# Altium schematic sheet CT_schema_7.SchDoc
size 278 x 170 mm
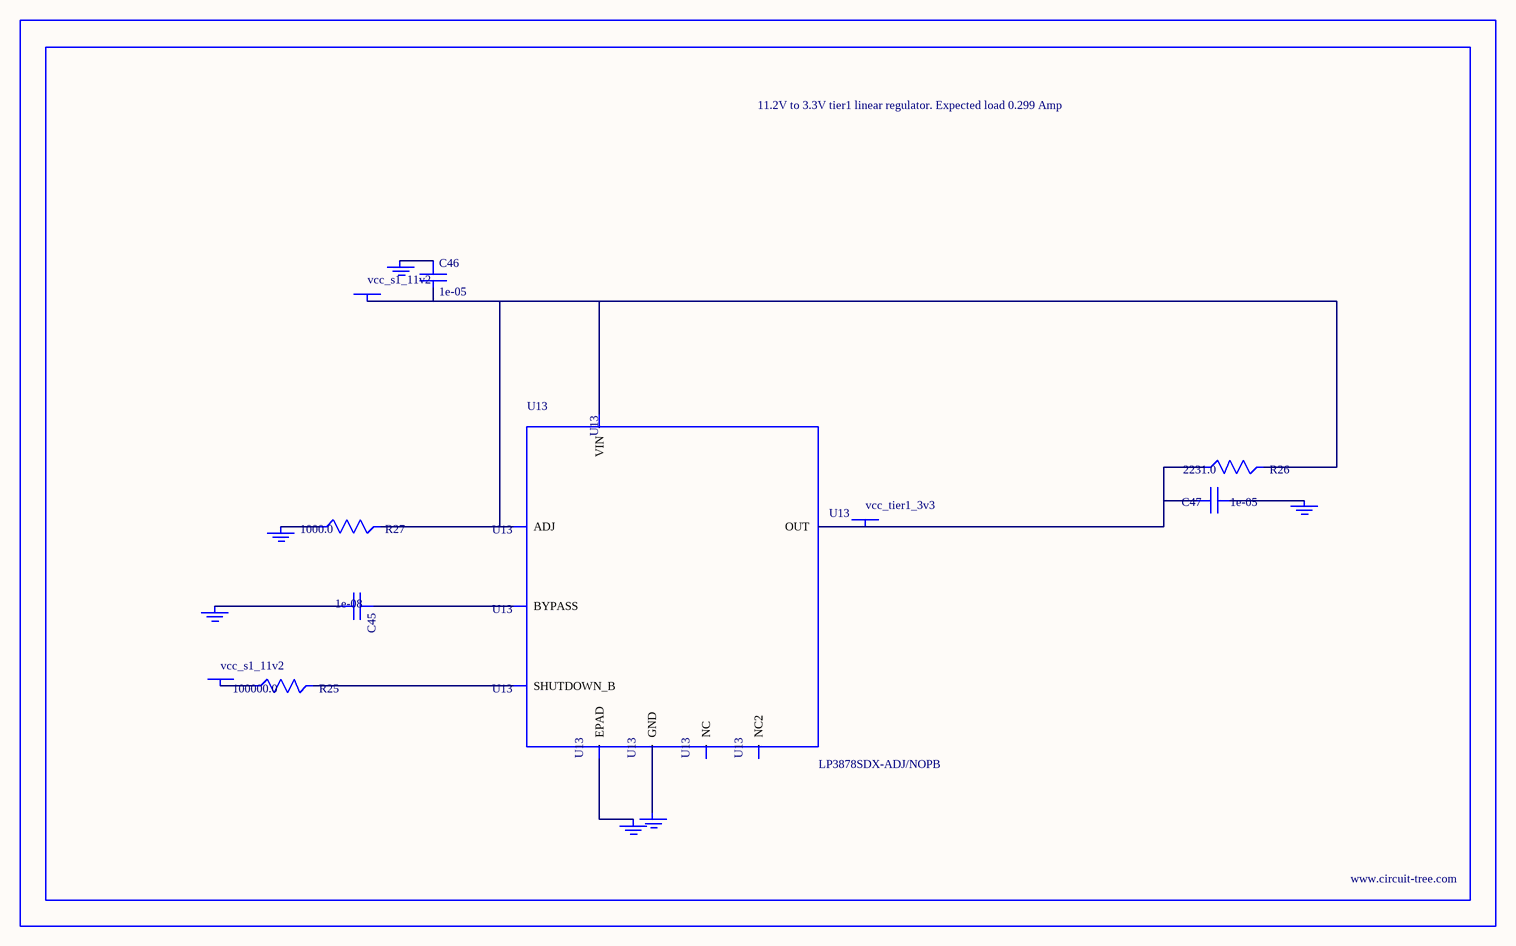
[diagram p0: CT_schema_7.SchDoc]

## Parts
BORDER6  (no value)
C45  1e-08  [C0402]
C46  1e-05  [C1210]
C47  1e-05  [C1210]
GND_INSTANCE_6_0  (no value)
GND_INSTANCE_6_1  (no value)
GND_INSTANCE_6_2  (no value)
GND_INSTANCE_6_3  (no value)
GND_INSTANCE_6_4  (no value)
GND_INSTANCE_6_5  (no value)
POWER_INSTANCE_6_0  vcc_s1_11v2
POWER_INSTANCE_6_1  vcc_s1_11v2
POWER_INSTANCE_6_2  vcc_tier1_3v3
R25  100000.0  [R0603]
R26  2231.0  [R0603]
R27  1000.0  [R0603]
U13  LP3878SDX-ADJ/NOPB  [WSON-8]

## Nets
NetC45_1: C45.1 U13.1(BYPASS)
NetC45_2: C45.2 GND_INSTANCE_6_0.0(GND)
NetC46_1: C46.1 GND_INSTANCE_6_1.0(GND)
NetC46_2: C46.2 POWER_INSTANCE_6_0.0(PWR) R26.2 R27.2 U13.4(VIN) U13.6(ADJ)
NetC47_1: C47.1 GND_INSTANCE_6_2.0(GND)
NetC47_2: C47.2 POWER_INSTANCE_6_2.0(PWR) R26.1 U13.5(OUT)
NetGND_INSTANCE_6_3_0: GND_INSTANCE_6_3.0(GND) R27.1
NetGND_INSTANCE_6_4_0: GND_INSTANCE_6_4.0(GND) U13.PAD(EPAD)
NetGND_INSTANCE_6_5_0: GND_INSTANCE_6_5.0(GND) U13.3(GND)
NetPOWER_INSTANCE_6_1_0: POWER_INSTANCE_6_1.0(PWR) R25.1
NetR25_2: R25.2 U13.8(SHUTDOWN_B)

Not connected (* = marked no-connect by the designer): U13 2(NC) 7(NC2)

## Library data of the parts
BORDER6 = BORDER_PAGE6
C45 = C0402C103K3RAC
C46 = C1210C106K5PACTU
C47 = GRM32DR61E106MA12L
GND_INSTANCE_6_0-GND_INSTANCE_6_5 = GND
POWER_INSTANCE_6_0-POWER_INSTANCE_6_2 = PWR
R25 = RC0603JR-07100KL
R26 = R26
R27 = RC0603JR-071KL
